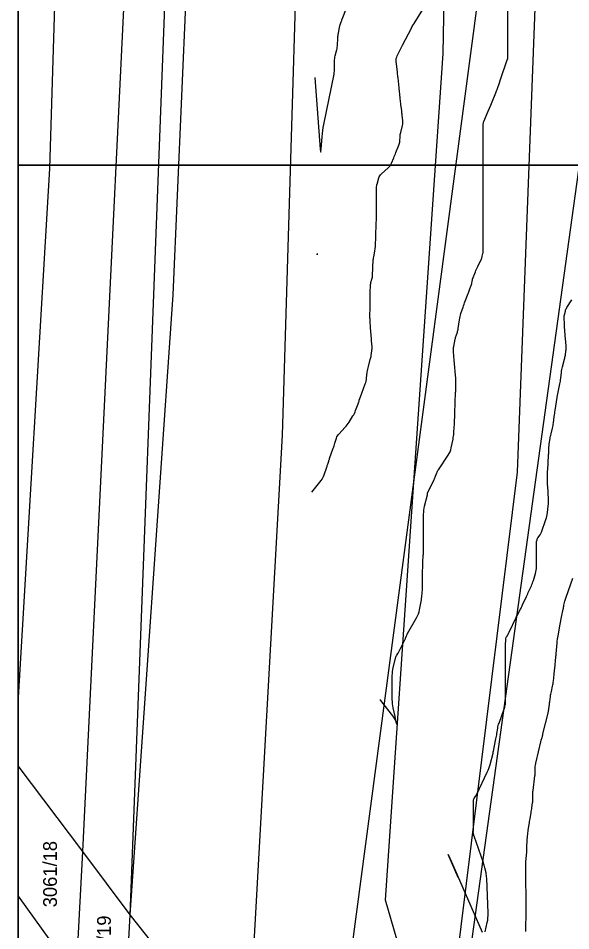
# Model space of a CAD drawing. Extents: x -534410 to -534262, y -1190162 to -1189584.
# Drawn here: x -534410.1 to -534375.9, y -1189946.9 to -1189890.4 of the extents above; entities that cross this region are included whole.
import ezdxf

# ---------------------------------------------------------------- set-up
doc = ezdxf.new("R2010")
doc.units = 0
for name, color, linetype in [('30', 7, 'Continuous'), ('31', 7, 'Continuous'), ('_rámeček', 7, 'Continuous'), ('_rámeček_mřížka', 7, 'Continuous'), ('Hranice parcel', 7, 'Continuous'), ('Parcelní čísla', 7, 'Continuous')]:
    doc.layers.add(name, color=color, linetype=linetype)

msp = doc.modelspace()

# ---------------------------------------------------------------- linework, layer by layer
at = {"layer": '30'}
for points in [[(-534391.934, -1189919.721), (-534391.36, -1189919.002), (-534391.301, -1189918.921), (-534391.25, -1189918.836), (-534391.206, -1189918.747), (-534391.171, -1189918.654), (-534391.01, -1189918.171), (-534390.995, -1189918.126), (-534390.981, -1189918.081), (-534390.966, -1189918.036), (-534390.952, -1189917.991), (-534390.895, -1189917.811), (-534390.881, -1189917.766), (-534390.866, -1189917.721), (-534390.851, -1189917.676), (-534390.836, -1189917.631), (-534390.612, -1189916.998), (-534390.585, -1189916.921), (-534390.559, -1189916.844), (-534390.534, -1189916.767), (-534390.509, -1189916.69), (-534390.411, -1189916.38), (-534390.383, -1189916.305), (-534390.347, -1189916.235), (-534390.303, -1189916.168), (-534390.252, -1189916.107), (-534389.887, -1189915.713), (-534389.817, -1189915.634), (-534389.751, -1189915.552), (-534389.688, -1189915.468), (-534389.629, -1189915.38), (-534389.39, -1189915.003), (-534389.341, -1189914.923), (-534389.298, -1189914.84), (-534389.259, -1189914.755), (-534389.225, -1189914.667), (-534389.073, -1189914.243), (-534389.054, -1189914.189), (-534389.035, -1189914.135), (-534389.016, -1189914.081), (-534388.997, -1189914.027), (-534388.923, -1189913.81), (-534388.904, -1189913.756), (-534388.885, -1189913.702), (-534388.865, -1189913.648), (-534388.845, -1189913.594), (-534388.627, -1189913.018), (-534388.597, -1189912.931), (-534388.573, -1189912.842), (-534388.554, -1189912.751), (-534388.542, -1189912.66), (-534388.502, -1189912.29), (-534388.49, -1189912.198), (-534388.474, -1189912.107), (-534388.455, -1189912.017), (-534388.432, -1189911.927), (-534388.317, -1189911.513), (-534388.3, -1189911.448), (-534388.285, -1189911.382), (-534388.272, -1189911.315), (-534388.261, -1189911.248), (-534388.22, -1189910.967), (-534388.213, -1189910.906), (-534388.209, -1189910.844), (-534388.208, -1189910.783), (-534388.211, -1189910.721), (-534388.237, -1189910.35), (-534388.246, -1189910.227), (-534388.295, -1189909.547), (-534388.305, -1189909.406), (-534388.315, -1189909.266), (-534388.335, -1189908.985), (-534388.339, -1189908.915), (-534388.342, -1189908.844), (-534388.342, -1189908.774), (-534388.341, -1189908.704), (-534388.331, -1189908.407), (-534388.329, -1189908.334), (-534388.328, -1189908.261), (-534388.327, -1189908.188), (-534388.327, -1189908.115), (-534388.327, -1189907.574), (-534388.326, -1189907.501), (-534388.326, -1189907.428), (-534388.324, -1189907.355), (-534388.322, -1189907.282), (-534388.313, -1189906.959), (-534388.309, -1189906.902), (-534388.302, -1189906.846), (-534388.292, -1189906.79), (-534388.278, -1189906.735), (-534388.214, -1189906.515), (-534388.2, -1189906.46), (-534388.189, -1189906.405), (-534388.181, -1189906.348), (-534388.177, -1189906.291), (-534388.13, -1189905.324), (-534388.127, -1189905.275), (-534388.122, -1189905.227), (-534388.115, -1189905.179), (-534388.106, -1189905.131), (-534388.062, -1189904.91), (-534388.056, -1189904.877), (-534388.05, -1189904.844), (-534388.044, -1189904.812), (-534388.038, -1189904.779), (-534388.016, -1189904.648), (-534388.011, -1189904.616), (-534388.007, -1189904.583), (-534388.004, -1189904.55), (-534388.003, -1189904.517), (-534387.961, -1189903.116), (-534387.96, -1189903.088), (-534387.958, -1189903.061), (-534387.956, -1189903.034), (-534387.952, -1189903.007), (-534387.937, -1189902.891), (-534387.934, -1189902.868), (-534387.932, -1189902.844), (-534387.931, -1189902.821), (-534387.931, -1189902.798), (-534387.931, -1189902.68), (-534387.931, -1189902.633), (-534387.931, -1189902.609), (-534387.931, -1189901.08), (-534387.931, -1189901.033), (-534387.931, -1189900.985), (-534387.931, -1189900.887), (-534387.931, -1189900.866), (-534387.93, -1189900.845), (-534387.929, -1189900.823), (-534387.927, -1189900.802), (-534387.917, -1189900.718), (-534387.914, -1189900.697), (-534387.91, -1189900.676), (-534387.906, -1189900.655), (-534387.9, -1189900.634), (-534387.785, -1189900.247), (-534387.76, -1189900.178), (-534387.726, -1189900.115), (-534387.683, -1189900.057), (-534387.632, -1189900.005), (-534387.212, -1189899.631), (-534387.149, -1189899.568), (-534387.093, -1189899.499), (-534387.046, -1189899.424), (-534387.006, -1189899.344), (-534386.865, -1189899.011), (-534386.83, -1189898.928), (-534386.795, -1189898.844), (-534386.761, -1189898.76), (-534386.727, -1189898.677), (-534386.544, -1189898.216), (-534386.522, -1189898.154), (-534386.505, -1189898.091), (-534386.493, -1189898.026), (-534386.486, -1189897.961), (-534386.471, -1189897.696), (-534386.465, -1189897.63), (-534386.457, -1189897.565), (-534386.446, -1189897.5), (-534386.431, -1189897.435), (-534386.324, -1189896.994), (-534386.309, -1189896.919), (-534386.301, -1189896.844), (-534386.299, -1189896.768), (-534386.304, -1189896.692), (-534386.338, -1189896.386), (-534386.346, -1189896.309), (-534386.355, -1189896.233), (-534386.364, -1189896.157), (-534386.373, -1189896.08), (-534386.418, -1189895.714), (-534386.428, -1189895.627), (-534386.439, -1189895.541), (-534386.448, -1189895.454), (-534386.458, -1189895.367), (-534386.495, -1189895.019), (-534386.504, -1189894.932), (-534386.513, -1189894.845), (-534386.523, -1189894.757), (-534386.532, -1189894.67), (-534386.6, -1189894.043), (-534386.603, -1189894.012), (-534386.606, -1189893.981), (-534386.61, -1189893.95), (-534386.613, -1189893.919), (-534386.625, -1189893.795), (-534386.628, -1189893.764), (-534386.632, -1189893.733), (-534386.635, -1189893.702), (-534386.638, -1189893.671), (-534386.709, -1189893.028), (-534386.712, -1189892.937), (-534386.704, -1189892.849), (-534386.682, -1189892.762), (-534386.649, -1189892.678), (-534386.488, -1189892.346), (-534386.448, -1189892.263), (-534386.407, -1189892.18), (-534386.365, -1189892.098), (-534386.323, -1189892.016), (-534385.769, -1189890.961), (-534385.756, -1189890.937), (-534385.742, -1189890.913), (-534385.728, -1189890.889), (-534385.714, -1189890.866), (-534385.655, -1189890.773), (-534385.64, -1189890.75), (-534385.626, -1189890.727), (-534385.611, -1189890.704), (-534385.597, -1189890.68), (-534385.058, -1189889.813)], [(-534381.198, -1189946.974), (-534381.07, -1189946.397), (-534381.043, -1189946.252), (-534381.026, -1189946.106), (-534381.017, -1189945.96), (-534381.018, -1189945.813), (-534381.106, -1189943.637), (-534381.111, -1189943.556), (-534381.119, -1189943.476), (-534381.132, -1189943.397), (-534381.147, -1189943.318), (-534381.217, -1189943.002), (-534381.235, -1189942.924), (-534381.256, -1189942.846), (-534381.279, -1189942.769), (-534381.305, -1189942.692), (-534381.886, -1189941.039), (-534381.893, -1189941.02), (-534381.899, -1189941.001), (-534381.904, -1189940.981), (-534381.909, -1189940.962), (-534381.928, -1189940.884), (-534381.932, -1189940.864), (-534381.935, -1189940.844), (-534381.937, -1189940.824), (-534381.937, -1189940.804), (-534381.933, -1189940.703), (-534381.932, -1189940.68), (-534381.932, -1189940.656), (-534381.932, -1189940.633), (-534381.931, -1189940.609), (-534381.931, -1189939.08), (-534381.931, -1189939.056), (-534381.931, -1189939.033), (-534381.931, -1189939.009), (-534381.93, -1189938.986), (-534381.927, -1189938.881), (-534381.925, -1189938.863), (-534381.923, -1189938.845), (-534381.92, -1189938.827), (-534381.915, -1189938.809), (-534381.895, -1189938.738), (-534381.889, -1189938.721), (-534381.883, -1189938.704), (-534381.874, -1189938.687), (-534381.865, -1189938.672), (-534381.779, -1189938.543), (-534381.761, -1189938.516), (-534381.745, -1189938.488), (-534381.73, -1189938.46), (-534381.716, -1189938.432), (-534381.068, -1189937.07), (-534381.017, -1189936.956), (-534380.972, -1189936.841), (-534380.932, -1189936.723), (-534380.898, -1189936.603), (-534380.713, -1189935.899), (-534380.711, -1189935.889), (-534380.709, -1189935.879), (-534380.707, -1189935.87), (-534380.706, -1189935.86), (-534380.701, -1189935.82), (-534380.7, -1189935.81), (-534380.698, -1189935.8), (-534380.696, -1189935.79), (-534380.694, -1189935.78), (-534380.533, -1189935.007), (-534380.516, -1189934.925), (-534380.501, -1189934.844), (-534380.487, -1189934.763), (-534380.474, -1189934.681), (-534380.423, -1189934.354), (-534380.408, -1189934.273), (-534380.389, -1189934.192), (-534380.367, -1189934.113), (-534380.34, -1189934.035), (-534380.017, -1189933.156), (-534380.006, -1189933.126), (-534379.996, -1189933.095), (-534379.988, -1189933.064), (-534379.98, -1189933.033), (-534379.952, -1189932.907), (-534379.946, -1189932.876), (-534379.941, -1189932.844), (-534379.939, -1189932.812), (-534379.938, -1189932.78), (-534379.938, -1189930.892), (-534379.938, -1189930.868), (-534379.937, -1189930.845), (-534379.937, -1189930.821), (-534379.936, -1189930.797), (-534379.933, -1189930.703), (-534379.932, -1189930.68), (-534379.932, -1189930.656), (-534379.931, -1189930.633), (-534379.931, -1189930.609), (-534379.931, -1189929.08), (-534379.931, -1189929.056), (-534379.931, -1189929.033), (-534379.93, -1189929.009), (-534379.93, -1189928.986), (-534379.926, -1189928.882), (-534379.925, -1189928.863), (-534379.923, -1189928.845), (-534379.92, -1189928.826), (-534379.916, -1189928.808), (-534379.897, -1189928.736), (-534379.892, -1189928.718), (-534379.885, -1189928.701), (-534379.877, -1189928.684), (-534379.868, -1189928.668), (-534379.779, -1189928.527), (-534379.762, -1189928.498), (-534379.745, -1189928.469), (-534379.729, -1189928.439), (-534379.714, -1189928.408), (-534379.283, -1189927.502), (-534379.251, -1189927.435), (-534379.218, -1189927.369), (-534379.185, -1189927.303), (-534379.151, -1189927.237), (-534379.014, -1189926.975), (-534378.98, -1189926.91), (-534378.947, -1189926.844), (-534378.914, -1189926.777), (-534378.883, -1189926.71), (-534378.64, -1189926.188), (-534378.602, -1189926.106), (-534378.564, -1189926.023), (-534378.527, -1189925.941), (-534378.489, -1189925.859), (-534378.339, -1189925.53), (-534378.303, -1189925.447), (-534378.27, -1189925.363), (-534378.24, -1189925.278), (-534378.213, -1189925.192), (-534378.086, -1189924.762), (-534378.06, -1189924.661), (-534378.042, -1189924.559), (-534378.03, -1189924.455), (-534378.027, -1189924.351), (-534378.027, -1189923.199), (-534378.027, -1189923.164), (-534378.027, -1189923.128), (-534378.027, -1189923.093), (-534378.027, -1189923.057), (-534378.028, -1189922.904), (-534378.027, -1189922.874), (-534378.025, -1189922.845), (-534378.021, -1189922.816), (-534378.015, -1189922.787), (-534377.988, -1189922.671), (-534377.98, -1189922.643), (-534377.969, -1189922.615), (-534377.956, -1189922.59), (-534377.94, -1189922.565), (-534377.801, -1189922.374), (-534377.774, -1189922.333), (-534377.75, -1189922.291), (-534377.729, -1189922.247), (-534377.711, -1189922.201), (-534377.442, -1189921.418), (-534377.409, -1189921.316), (-534377.383, -1189921.213), (-534377.361, -1189921.109), (-534377.345, -1189921.003), (-534377.291, -1189920.578), (-534377.28, -1189920.472), (-534377.274, -1189920.365), (-534377.273, -1189920.259), (-534377.277, -1189920.152), (-534377.326, -1189919.358), (-534377.329, -1189919.306), (-534377.332, -1189919.255), (-534377.334, -1189919.204), (-534377.336, -1189919.152), (-534377.343, -1189918.947), (-534377.345, -1189918.896), (-534377.345, -1189918.845), (-534377.345, -1189918.793), (-534377.343, -1189918.742), (-534377.336, -1189918.537), (-534377.334, -1189918.485), (-534377.332, -1189918.434), (-534377.329, -1189918.383), (-534377.326, -1189918.331), (-534377.272, -1189917.443), (-534377.268, -1189917.383), (-534377.265, -1189917.323), (-534377.263, -1189917.263), (-534377.26, -1189917.203), (-534377.252, -1189916.964), (-534377.249, -1189916.904), (-534377.245, -1189916.845), (-534377.238, -1189916.785), (-534377.23, -1189916.726), (-534377.178, -1189916.403), (-534377.166, -1189916.33), (-534377.152, -1189916.257), (-534377.136, -1189916.184), (-534377.119, -1189916.112), (-534377.031, -1189915.762), (-534377.012, -1189915.68), (-534376.995, -1189915.597), (-534376.98, -1189915.513), (-534376.968, -1189915.429), (-534376.918, -1189915.033), (-534376.905, -1189914.939), (-534376.892, -1189914.845), (-534376.879, -1189914.751), (-534376.865, -1189914.657), (-534376.74, -1189913.85), (-534376.739, -1189913.845), (-534376.737, -1189913.836), (-534376.571, -1189913.021), (-534376.555, -1189912.933), (-534376.54, -1189912.844), (-534376.527, -1189912.755), (-534376.517, -1189912.665), (-534376.479, -1189912.307), (-534376.468, -1189912.217), (-534376.453, -1189912.129), (-534376.435, -1189912.041), (-534376.413, -1189911.953), (-534376.284, -1189911.476), (-534376.269, -1189911.414), (-534376.255, -1189911.352), (-534376.243, -1189911.289), (-534376.233, -1189911.225), (-534376.195, -1189910.961), (-534376.188, -1189910.902), (-534376.185, -1189910.844), (-534376.184, -1189910.786), (-534376.187, -1189910.728), (-534376.211, -1189910.377), (-534376.219, -1189910.26), (-534376.276, -1189909.449), (-534376.29, -1189909.247), (-534376.309, -1189908.963), (-534376.311, -1189908.904), (-534376.309, -1189908.845), (-534376.301, -1189908.787), (-534376.29, -1189908.729), (-534376.233, -1189908.498), (-534376.217, -1189908.441), (-534376.196, -1189908.386), (-534376.171, -1189908.333), (-534376.141, -1189908.282), (-534375.836, -1189907.806)], [(-534382.868, -1189943.609), (-534383.492, -1189942.189), (-534383.296, -1189942.636), (-534381.381, -1189946.992)]]:
    msp.add_lwpolyline(points, dxfattribs=at)
at = {"layer": '31'}
for points in [[(-534387.715, -1189932.58), (-534387.697, -1189932.621), (-534387.694, -1189932.628), (-534387.691, -1189932.634), (-534387.687, -1189932.64), (-534387.682, -1189932.646), (-534386.878, -1189933.668), (-534386.808, -1189933.769), (-534386.752, -1189933.876), (-534386.71, -1189933.99), (-534386.682, -1189934.109), (-534386.704, -1189933.987), (-534386.727, -1189933.865), (-534386.752, -1189933.743), (-534386.778, -1189933.621), (-534386.896, -1189933.099), (-534386.922, -1189932.972), (-534386.94, -1189932.843), (-534386.95, -1189932.713), (-534386.954, -1189932.583), (-534386.954, -1189931.094), (-534386.95, -1189930.97), (-534386.939, -1189930.846), (-534386.92, -1189930.724), (-534386.893, -1189930.603), (-534386.725, -1189929.934), (-534386.717, -1189929.906), (-534386.706, -1189929.879), (-534386.693, -1189929.853), (-534386.678, -1189929.828), (-534386.612, -1189929.729), (-534386.596, -1189929.704), (-534386.58, -1189929.679), (-534386.566, -1189929.653), (-534386.552, -1189929.627), (-534386.193, -1189928.916), (-534386.175, -1189928.88), (-534386.158, -1189928.844), (-534386.143, -1189928.807), (-534386.128, -1189928.769), (-534386.072, -1189928.619), (-534386.057, -1189928.582), (-534386.04, -1189928.546), (-534386.023, -1189928.51), (-534386.004, -1189928.475), (-534385.449, -1189927.504), (-534385.388, -1189927.386), (-534385.337, -1189927.264), (-534385.296, -1189927.138), (-534385.266, -1189927.008), (-534385.15, -1189926.395), (-534385.135, -1189926.306), (-534385.123, -1189926.218), (-534385.115, -1189926.129), (-534385.109, -1189926.039), (-534385.093, -1189925.666), (-534385.09, -1189925.584), (-534385.087, -1189925.502), (-534385.085, -1189925.42), (-534385.084, -1189925.337), (-534385.081, -1189925.009), (-534385.08, -1189924.927), (-534385.079, -1189924.845), (-534385.077, -1189924.762), (-534385.075, -1189924.68), (-534385.065, -1189924.314), (-534385.063, -1189924.238), (-534385.06, -1189924.163), (-534385.057, -1189924.087), (-534385.053, -1189924.011), (-534385.038, -1189923.709), (-534385.034, -1189923.633), (-534385.031, -1189923.558), (-534385.028, -1189923.482), (-534385.026, -1189923.406), (-534385.016, -1189923.023), (-534385.014, -1189922.934), (-534385.013, -1189922.844), (-534385.012, -1189922.755), (-534385.012, -1189922.666), (-534385.012, -1189921.093), (-534385.008, -1189920.969), (-534384.997, -1189920.846), (-534384.979, -1189920.724), (-534384.953, -1189920.603), (-534384.78, -1189919.894), (-534384.779, -1189919.886), (-534384.777, -1189919.878), (-534384.777, -1189919.87), (-534384.777, -1189919.861), (-534384.777, -1189919.828), (-534384.776, -1189919.819), (-534384.775, -1189919.811), (-534384.772, -1189919.804), (-534384.769, -1189919.796), (-534384.366, -1189918.945), (-534384.343, -1189918.895), (-534384.32, -1189918.844), (-534384.299, -1189918.793), (-534384.278, -1189918.741), (-534384.197, -1189918.534), (-534384.176, -1189918.483), (-534384.152, -1189918.433), (-534384.125, -1189918.385), (-534384.095, -1189918.338), (-534383.496, -1189917.438), (-534383.432, -1189917.332), (-534383.379, -1189917.221), (-534383.337, -1189917.106), (-534383.306, -1189916.986), (-534383.191, -1189916.44), (-534383.173, -1189916.346), (-534383.158, -1189916.252), (-534383.147, -1189916.157), (-534383.139, -1189916.061), (-534383.111, -1189915.648), (-534383.106, -1189915.568), (-534383.102, -1189915.487), (-534383.098, -1189915.407), (-534383.095, -1189915.327), (-534383.085, -1189915.005), (-534383.082, -1189914.925), (-534383.08, -1189914.844), (-534383.077, -1189914.764), (-534383.075, -1189914.684), (-534383.065, -1189914.314), (-534383.063, -1189914.238), (-534383.06, -1189914.163), (-534383.057, -1189914.087), (-534383.053, -1189914.011), (-534383.037, -1189913.709), (-534383.034, -1189913.634), (-534383.031, -1189913.558), (-534383.028, -1189913.482), (-534383.026, -1189913.407), (-534383.016, -1189913.014), (-534383.015, -1189912.929), (-534383.016, -1189912.845), (-534383.02, -1189912.76), (-534383.026, -1189912.676), (-534383.061, -1189912.254), (-534383.082, -1189912.001), (-534383.122, -1189911.536), (-534383.141, -1189911.306), (-534383.167, -1189910.998), (-534383.17, -1189910.922), (-534383.169, -1189910.845), (-534383.161, -1189910.769), (-534383.149, -1189910.693), (-534383.058, -1189910.249), (-534383.046, -1189910.193), (-534383.031, -1189910.137), (-534383.015, -1189910.082), (-534382.998, -1189910.028), (-534382.923, -1189909.811), (-534382.906, -1189909.756), (-534382.891, -1189909.701), (-534382.879, -1189909.645), (-534382.869, -1189909.588), (-534382.791, -1189909.044), (-534382.775, -1189908.945), (-534382.754, -1189908.847), (-534382.729, -1189908.749), (-534382.7, -1189908.653), (-534382.573, -1189908.269), (-534382.541, -1189908.174), (-534382.507, -1189908.078), (-534382.472, -1189907.984), (-534382.436, -1189907.89), (-534382.251, -1189907.421), (-534382.228, -1189907.364), (-534382.206, -1189907.306), (-534382.185, -1189907.249), (-534382.163, -1189907.191), (-534382.059, -1189906.905), (-534382.049, -1189906.875), (-534382.04, -1189906.844), (-534382.033, -1189906.813), (-534382.027, -1189906.781), (-534382.007, -1189906.654), (-534382.002, -1189906.622), (-534381.994, -1189906.591), (-534381.986, -1189906.56), (-534381.975, -1189906.53), (-534381.807, -1189906.073), (-534381.774, -1189905.988), (-534381.739, -1189905.903), (-534381.702, -1189905.819), (-534381.663, -1189905.736), (-534381.436, -1189905.271), (-534381.417, -1189905.23), (-534381.402, -1189905.189), (-534381.388, -1189905.147), (-534381.377, -1189905.104), (-534381.338, -1189904.931), (-534381.329, -1189904.888), (-534381.323, -1189904.844), (-534381.32, -1189904.8), (-534381.318, -1189904.756), (-534381.318, -1189896.951), (-534381.316, -1189896.898), (-534381.308, -1189896.847), (-534381.295, -1189896.796), (-534381.278, -1189896.746), (-534381.017, -1189896.118), (-534380.856, -1189895.732), (-534380.816, -1189895.635), (-534380.544, -1189894.98), (-534380.516, -1189894.912), (-534380.49, -1189894.844), (-534380.464, -1189894.775), (-534380.44, -1189894.706), (-534380.321, -1189894.36), (-534380.273, -1189894.222), (-534380.249, -1189894.153), (-534379.83, -1189892.938), (-534379.805, -1189892.865), (-534379.802, -1189892.855), (-534379.799, -1189892.844), (-534379.798, -1189892.833), (-534379.798, -1189892.822), (-534379.798, -1189886.856)], [(-534391.748, -1189894.03), (-534391.417, -1189898.462), (-534391.402, -1189898.605), (-534391.388, -1189898.653), (-534391.374, -1189898.605), (-534391.36, -1189898.462), (-534391.303, -1189897.696), (-534391.285, -1189897.505), (-534391.262, -1189897.315), (-534391.233, -1189897.126), (-534391.198, -1189896.937), (-534390.564, -1189893.818), (-534390.547, -1189893.722), (-534390.535, -1189893.625), (-534390.528, -1189893.528), (-534390.526, -1189893.431), (-534390.529, -1189893.005), (-534390.527, -1189892.925), (-534390.52, -1189892.846), (-534390.507, -1189892.768), (-534390.488, -1189892.69), (-534390.404, -1189892.381), (-534390.385, -1189892.303), (-534390.37, -1189892.225), (-534390.36, -1189892.146), (-534390.354, -1189892.066), (-534390.328, -1189891.569), (-534390.323, -1189891.496), (-534390.316, -1189891.423), (-534390.306, -1189891.35), (-534390.293, -1189891.278), (-534390.227, -1189890.934), (-534390.218, -1189890.89), (-534390.207, -1189890.845), (-534390.194, -1189890.802), (-534390.18, -1189890.758), (-534390.119, -1189890.585), (-534390.104, -1189890.542), (-534390.088, -1189890.499), (-534390.072, -1189890.456), (-534390.056, -1189890.413), (-534389.793, -1189889.733)], [(-534378.686, -1189946.959), (-534378.679, -1189946.844), (-534378.674, -1189946.729), (-534378.672, -1189946.614), (-534378.666, -1189945.96), (-534378.666, -1189945.922), (-534378.666, -1189945.883), (-534378.666, -1189945.806), (-534378.666, -1189945.767), (-534378.665, -1189945.729), (-534378.66, -1189945.075), (-534378.659, -1189944.96), (-534378.659, -1189944.845), (-534378.66, -1189944.729), (-534378.662, -1189944.614), (-534378.674, -1189943.947), (-534378.675, -1189943.913), (-534378.675, -1189943.879), (-534378.676, -1189943.811), (-534378.676, -1189943.777), (-534378.677, -1189943.743), (-534378.689, -1189943.065), (-534378.69, -1189942.955), (-534378.688, -1189942.845), (-534378.683, -1189942.735), (-534378.676, -1189942.625), (-534378.627, -1189942.027), (-534378.624, -1189941.997), (-534378.623, -1189941.966), (-534378.622, -1189941.935), (-534378.621, -1189941.904), (-534378.619, -1189941.781), (-534378.618, -1189941.75), (-534378.617, -1189941.72), (-534378.616, -1189941.689), (-534378.614, -1189941.658), (-534378.568, -1189941.023), (-534378.561, -1189940.934), (-534378.552, -1189940.845), (-534378.541, -1189940.756), (-534378.529, -1189940.667), (-534378.477, -1189940.313), (-534378.464, -1189940.225), (-534378.45, -1189940.137), (-534378.436, -1189940.048), (-534378.421, -1189939.96), (-534378.355, -1189939.578), (-534378.343, -1189939.505), (-534378.331, -1189939.431), (-534378.319, -1189939.358), (-534378.308, -1189939.285), (-534378.259, -1189938.969), (-534378.251, -1189938.907), (-534378.245, -1189938.844), (-534378.242, -1189938.781), (-534378.242, -1189938.718), (-534378.246, -1189938.466), (-534378.245, -1189938.403), (-534378.243, -1189938.34), (-534378.238, -1189938.278), (-534378.232, -1189938.215), (-534378.116, -1189937.295), (-534378.111, -1189937.25), (-534378.107, -1189937.205), (-534378.106, -1189937.16), (-534378.106, -1189937.115), (-534378.11, -1189936.926), (-534378.11, -1189936.885), (-534378.108, -1189936.845), (-534378.105, -1189936.804), (-534378.1, -1189936.764), (-534378.078, -1189936.602), (-534378.071, -1189936.562), (-534378.064, -1189936.522), (-534378.056, -1189936.482), (-534378.048, -1189936.442), (-534377.757, -1189935.206), (-534377.75, -1189935.177), (-534377.742, -1189935.147), (-534377.734, -1189935.118), (-534377.725, -1189935.09), (-534377.676, -1189934.935), (-534377.668, -1189934.908), (-534377.654, -1189934.863), (-534377.652, -1189934.854), (-534377.65, -1189934.844), (-534377.648, -1189934.835), (-534377.646, -1189934.826), (-534377.636, -1189934.761), (-534377.633, -1189934.747), (-534377.631, -1189934.733), (-534377.628, -1189934.719), (-534377.624, -1189934.705), (-534377.304, -1189933.427), (-534377.291, -1189933.369), (-534377.279, -1189933.312), (-534377.269, -1189933.254), (-534377.261, -1189933.195), (-534377.231, -1189932.961), (-534377.224, -1189932.903), (-534377.216, -1189932.845), (-534377.209, -1189932.786), (-534377.201, -1189932.728), (-534377.154, -1189932.387), (-534377.143, -1189932.311), (-534377.13, -1189932.235), (-534377.116, -1189932.159), (-534377.1, -1189932.084), (-534377.027, -1189931.755), (-534377.011, -1189931.675), (-534376.996, -1189931.595), (-534376.984, -1189931.514), (-534376.974, -1189931.433), (-534376.929, -1189931.032), (-534376.918, -1189930.938), (-534376.908, -1189930.844), (-534376.899, -1189930.75), (-534376.89, -1189930.656), (-534376.825, -1189929.957), (-534376.823, -1189929.94), (-534376.821, -1189929.923), (-534376.819, -1189929.906), (-534376.816, -1189929.889), (-534376.806, -1189929.821), (-534376.803, -1189929.804), (-534376.801, -1189929.787), (-534376.799, -1189929.77), (-534376.798, -1189929.753), (-534376.741, -1189929.054), (-534376.731, -1189928.949), (-534376.718, -1189928.845), (-534376.703, -1189928.742), (-534376.685, -1189928.638), (-534376.548, -1189927.912), (-534376.467, -1189927.481), (-534376.37, -1189926.967), (-534376.358, -1189926.906), (-534376.346, -1189926.845), (-534376.332, -1189926.784), (-534376.318, -1189926.723), (-534376.259, -1189926.48), (-534376.243, -1189926.419), (-534376.226, -1189926.359), (-534376.207, -1189926.3), (-534376.187, -1189926.241), (-534375.76, -1189925.061)]]:
    msp.add_lwpolyline(points, dxfattribs=at)
for points in [[(-534391.612, -1189904.999), (-534391.618, -1189905.016), (-534391.612, -1189904.999), (-534391.606, -1189904.982)], [(-534391.6, -1189904.964), (-534391.593, -1189904.947), (-534391.6, -1189904.964), (-534391.606, -1189904.982)]]:
    msp.add_lwpolyline(points, close=True, dxfattribs=at)
at = {"layer": '_rámeček'}
msp.add_line((-534410.126, -1189584.47), (-534410.126, -1190161.97), dxfattribs=at)
for points in [[(-534410.126, -1189794.47), (-534261.626, -1189794.47), (-534261.626, -1189899.47), (-534410.126, -1189899.47)], [(-534410.126, -1189899.47), (-534261.626, -1189899.47), (-534261.626, -1190004.47), (-534410.126, -1190004.47)]]:
    msp.add_lwpolyline(points, close=True, dxfattribs=at)
at = {"layer": '_rámeček_mřížka'}
for p, q in [((-534410.126, -1189584.47), (-534410.126, -1190161.97)), ((-534407.126, -1189899.47), (-534410.126, -1189899.47))]:
    msp.add_line(p, q, dxfattribs=at)
at = {"layer": 'Hranice parcel'}
for p, q in [((-534403.19, -1189945.91), (-534398.3, -1189817.87)), ((-534391.18, -1189961.04), (-534385.61, -1189919.11)), ((-534406.13, -1189942), (-534410.126, -1189936.685)), ((-534406.54, -1189949.77), (-534406.13, -1189942)), ((-534403.19, -1189945.91), (-534406.13, -1189942)), ((-534410.126, -1189944.756), (-534406.54, -1189949.77)), ((-534403.61, -1189953.7), (-534403.19, -1189945.91)), ((-534395.93, -1189955.06), (-534403.19, -1189945.91))]:
    msp.add_line(p, q, dxfattribs=at)
for points in [[(-534395.93, -1189955.06), (-534393.76, -1189916.2), (-534389.49, -1189774.63), (-534390.92, -1189749.37)], [(-534385.61, -1189919.11), (-534380.06, -1189877.29), (-534378.67, -1189750.28)], [(-534383.94, -1189956.8), (-534379.19, -1189918.48), (-534376.74, -1189853.94), (-534375.92, -1189797.44), (-534376.41, -1189774.02), (-534378.12, -1189750.26)], [(-534385.61, -1189919.11), (-534383.81, -1189892.54), (-534382.22, -1189804.86), (-534381.85, -1189775.86), (-534383.09, -1189750.44)], [(-534406.13, -1189942), (-534403.45, -1189886.77), (-534402.68, -1189837.82), (-534401.95, -1189776.76), (-534406.3, -1189754), (-534406.48, -1189752.31)], [(-534373.61, -1189764.09), (-534375.04, -1189897.07), (-534384.28, -1189963.65)], [(-534410.126, -1189932.794), (-534408.16, -1189899.66), (-534406.57, -1189847.9), (-534405.68, -1189781.38), (-534406.95, -1189766.9)], [(-534403.19, -1189945.91), (-534400.52, -1189907.49), (-534398.39, -1189858.23), (-534398.3, -1189817.87)], [(-534383.94, -1189956.8), (-534387.37, -1189945.01), (-534385.61, -1189919.11)]]:
    msp.add_lwpolyline(points, dxfattribs=at)

# ---------------------------------------------------------------- texts
at = {"layer": 'Parcelní čísla'}
for s, p in [('3061/18', (-534407.732, -1189945.451)), ('3061/19', (-534404.39, -1189950.071))]:
    msp.add_text(s, height=0.85, rotation=90, dxfattribs=at).set_placement(p)

doc.saveas('drawing.dxf')
